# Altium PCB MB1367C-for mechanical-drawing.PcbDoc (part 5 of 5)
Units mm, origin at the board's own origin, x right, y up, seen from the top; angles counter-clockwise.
Board outline 70 x 82.5 mm, 4 copper layers (Top Layer, Signal Layer 1, Signal Layer 2, Bottom Layer), stack 1.614 mm thick; 191 components, 143 nets, 808 pads, 920 vias.
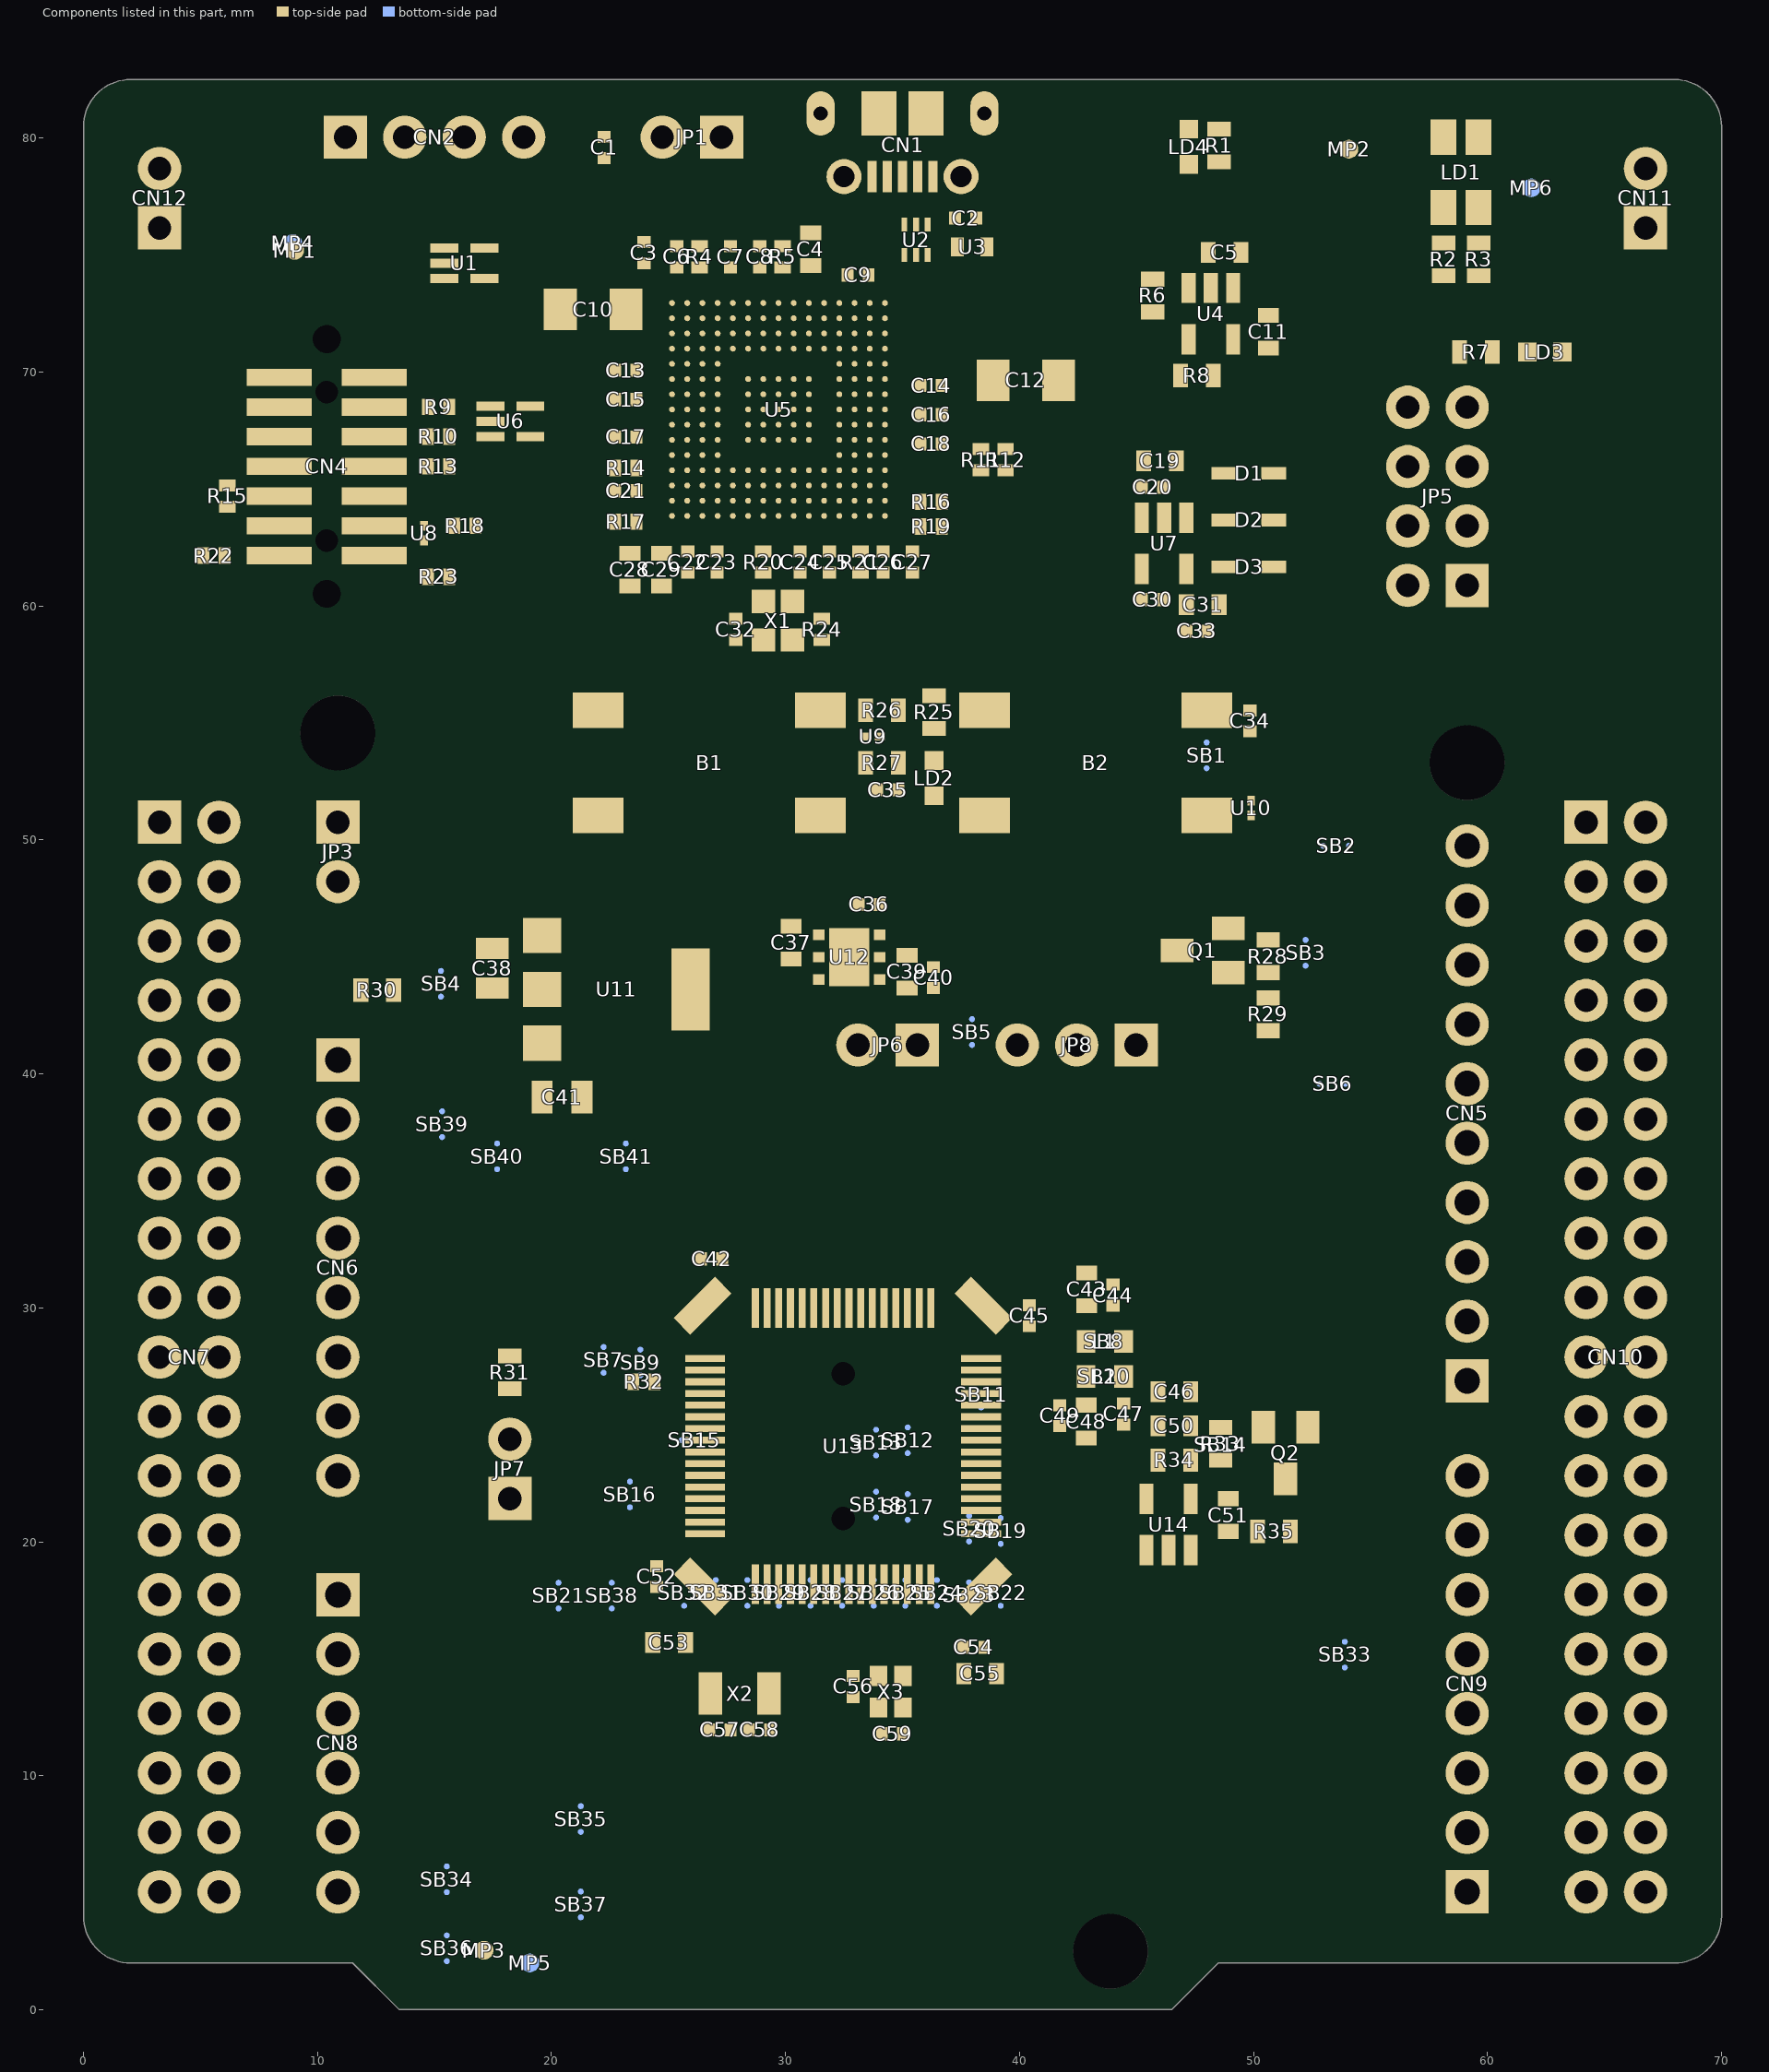
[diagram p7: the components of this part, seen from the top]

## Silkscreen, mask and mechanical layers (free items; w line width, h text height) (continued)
Drill Drawing:
  drawing of 339 lines, arcs and shapes, not listed
  text "« THE COMPONENTS WITH PLATED THROUGH HOLE (PTH) MAY BE WELDED (CABLED) IN \"PIN-IN-PASTE\" MODE (IF NECESSARY) »" at 16.925,136.875 h3.5
  text "PCB SPECIFICATIONS :" at 0.67,130.815 h3
  text "**Plating type :" at 117.72,130.465 h2.5
  text "A.   MATERIAL :" at 0.67,126.815 h3
  text "FR-4" at 39.17,126.815 h3
  text "TG-170" at 55.67,126.815 h3
  text "X  TG-150" at 73.92,126.815 h3
  text "TG-140" at 89.92,126.815 h3
  text "lead Gold" at 124.445,125.99 h2.5
  text "B.   MATERIAL FAMILY :" at 0.67,123.815 h3
  text "N/A" at 39.17,123.815 h3
  text "C.   SOLDERMASK COLOR :" at 0.67,120.815 h3
  text "GREEN" at 39.17,120.815 h3
  text "X  WHITE" at 55.67,120.815 h3
  text "RED" at 73.92,120.815 h3
  text "BLACK" at 89.92,120.815 h3
  text "D.   SILKSCREEN COLOR :" at 0.67,117.815 h3
  text "WHITE" at 39.17,117.815 h3
  text "YELLOW" at 55.67,117.815 h3
  text "BLACK" at 73.92,117.815 h3
  text "X  Blue ink PANTONE 2955" at 89.92,117.815 h3
  text "E.   SURFACE FINISH :" at 0.67,114.815 h3
  text "X  ENIG" at 39.17,114.815 h3
  text "IMMERSION SILVER" at 55.67,114.815 h3
  text "IMMERSION TIN" at 89.92,114.815 h3
  text "HASL" at 39.17,111.815 h3
  text "HASL (PB-FREE)" at 55.67,111.815 h3
  text "GOLDEN FINGER" at 89.92,111.815 h3
  text "F.   IMPEDANCE CONTROL :" at 0.67,108.815 h3
  text "NO" at 39.17,108.815 h3
  text "X  YES  (SEE IMPEDANCE TABLE FOR DETAIL INFORMATION)" at 55.67,108.815 h3
  text "G.   THROUGH VIA :" at 0.67,105.815 h3
  text "PLUG THE VIAS WHICH ARE COVERED WITH SOLDERMASK ONE OR TWO SIDE." at 39.17,105.815 h3
  text "PLUG MATERIAL :" at 39.17,102.815 h3
  text "X  SOLDERMASK" at 64.67,102.815 h3
  text "NON-CONDUCTIVE EPOXY." at 89.92,102.815 h3
  text "H.   STACK-UP :" at 0.67,99.815 h3
  text "SEE LAYER STACK-UP SEQUENCE FOR OVERALL THICKNESS." at 39.17,99.815 h3
  text "Layer" at 79.198,93.05 h2
  text "Name" at 87.572,93.05 h2
  text "Material" at 103.769,93.05 h2
  text "Thickness" at 118.323,93.05 h2
  text "Constant" at 130.278,93.05 h2
  text "Board Layer Stack" at 141.342,93.05 h2
  text "1" at 79.198,89.05 h2
  text "Top Overlay" at 87.572,89.05 h2
  text "PCB : TYPE 3" at 166.351,87.363 h3
  text "2" at 79.198,85.05 h2
  text "Top Solder" at 87.572,85.05 h2
  text "Solder Resist" at 103.769,85.05 h2
  text "0,015mm" at 118.323,85.05 h2
  text "3,5" at 130.278,85.05 h2
  text "ASPECT-RATIO, AXE Z :" at 166.351,81.863 h3
  text "3" at 79.198,81.05 h2
  text "Top Layer" at 87.572,81.05 h2
  text "Copper" at 103.769,81.05 h2
  text "0,042mm" at 118.323,81.05 h2
  text "4" at 79.198,77.05 h2
  text "Dielectric 1" at 87.572,77.05 h2
  text "PP-IT-180A" at 103.769,77.05 h2
  text "0,106mm" at 118.323,77.05 h2
  text "4,2" at 130.278,77.05 h2
  text "6:1 to 8:1 / LEVEL \"B\"" at 166.37,75.115 h3
  text "5" at 79.198,73.05 h2
  text "Signal Layer 1" at 87.572,73.05 h2
  text "Copper" at 103.769,73.05 h2
  text "0,035mm" at 118.323,73.05 h2
  text "6" at 79.198,69.05 h2
  text "Dielectric 2" at 87.572,69.05 h2
  text "FR4" at 103.769,69.05 h2
  text "1,248mm" at 118.323,69.05 h2
  text "4,2" at 130.278,69.05 h2
  text "MINIMUM PARAMETERS" at 166.595,65.99 h3
  text "7" at 79.198,65.05 h2
  text "Signal Layer 2" at 87.572,65.05 h2
  text "Copper" at 103.769,65.05 h2
  text "0,035mm" at 118.323,65.05 h2
  text "8" at 79.198,61.05 h2
  text "Dielectric 3" at 87.572,61.05 h2
  text "PP-IT-180A" at 103.769,61.05 h2
  text "0,106mm" at 118.323,61.05 h2
  text "4,2" at 130.278,61.05 h2
  text "DEFAULT" at 166.595,60.49 h3
  text "9" at 79.198,57.05 h2
  text "Bottom Layer" at 87.572,57.05 h2
  text "Copper" at 103.769,57.05 h2
  text "0,042mm" at 118.323,57.05 h2
  text "TRACKS : 0.120mm           / GAPS : 0.120mm" at 166.595,54.74 h3
  text "10" at 79.198,53.05 h2
  text "Bottom Solder" at 87.572,53.05 h2
  text "Solder Resist" at 103.769,53.05 h2
  text "0,015mm" at 118.323,53.05 h2
  text "3,5" at 130.278,53.05 h2
  text "11" at 79.198,49.05 h2
  text "Bottom Overlay" at 87.572,49.05 h2
  text "Symbol" at 87.771,42.179 h2.4
  text "Count" at 97.17,42.179 h2.4
  text "Hole Size" at 107.801,42.179 h2.4
  text "Plated" at 127.073,42.179 h2.4
  text "Hole Type" at 135.324,42.179 h2.4
  text "Drill Layer Pair" at 147.335,42.179 h2.4
  text "Via/Pad" at 170.115,42.179 h2.4
  text "Hole Length" at 179.958,42.179 h2.4
  text "Routed Path Length" at 198.115,42.179 h2.4
  text "920" at 97.17,38.036 h2
  text "0,200mm (7,87mil)" at 107.801,38.036 h2
  text "PTH" at 127.073,38.036 h2
  text "Round" at 135.324,38.036 h2
  text "Top Layer - Bottom Layer" at 147.335,38.036 h2
  text "Via" at 170.115,38.036 h2
  text "-" at 179.958,38.036 h2
  text "-" at 198.115,38.036 h2
  text "0,20" at 87.851,37.475 h1.84
  text "2" at 97.17,33.892 h2
  text "0,600mm (23,62mil)" at 107.801,33.892 h2
  text "PTH" at 127.073,33.892 h2
  text "Slot" at 135.324,33.892 h2
  text "Top Layer - Bottom Layer" at 147.335,33.892 h2
  text "Pad" at 170.115,33.892 h2
  text "1,300mm (51,18mil)" at 179.958,33.892 h2
  text "0,700mm (27,56mil)" at 198.115,33.892 h2
  text "0,60" at 87.851,33.332 h1.84
  text "2" at 97.17,29.749 h2
  text "0,900mm (35,43mil)" at 107.801,29.749 h2
  text "PTH" at 127.073,29.749 h2
  text "Round" at 135.324,29.749 h2
  text "Top Layer - Bottom Layer" at 147.335,29.749 h2
  text "Pad" at 170.115,29.749 h2
  text "-" at 179.958,29.749 h2
  text "-" at 198.115,29.749 h2
  text "0,90" at 87.851,29.189 h1.84
  text "2" at 97.17,25.606 h2
  text "0,970mm (38,19mil)" at 107.801,25.606 h2
  text "NPTH" at 127.073,25.606 h2
  text "Round" at 135.324,25.606 h2
  text "Top Layer - Bottom Layer" at 147.335,25.606 h2
  text "Pad" at 170.115,25.606 h2
  text "-" at 179.958,25.606 h2
  text "-" at 198.115,25.606 h2
  text "0,97" at 87.851,25.046 h1.84
  text "2" at 97.17,21.463 h2
  text "1,000mm (39,37mil)" at 107.801,21.463 h2
  text "NPTH" at 127.073,21.463 h2
  text "Round" at 135.324,21.463 h2
  text "Top Layer - Bottom Layer" at 147.335,21.463 h2
  text "Pad" at 170.115,21.463 h2
  text "-" at 179.958,21.463 h2
  text "-" at 198.115,21.463 h2
  text "1,00" at 87.851,20.903 h1.84
  text "103" at 97.17,17.32 h2
  text "1,000mm (39,37mil)" at 107.801,17.32 h2
  text "PTH" at 127.073,17.32 h2
  text "Round" at 135.324,17.32 h2
  text "Top Layer - Bottom Layer" at 147.335,17.32 h2
  text "Pad" at 170.115,17.32 h2
  text "-" at 179.958,17.32 h2
  text "-" at 198.115,17.32 h2
  text "1,00" at 87.851,16.76 h1.84
  text "32" at 97.17,13.177 h2
  text "1,100mm (43,31mil)" at 107.801,13.177 h2
  text "PTH" at 127.073,13.177 h2
  text "Round" at 135.324,13.177 h2
  text "Top Layer - Bottom Layer" at 147.335,13.177 h2
  text "Pad" at 170.115,13.177 h2
  text "-" at 179.958,13.177 h2
  text "-" at 198.115,13.177 h2
  text "1,10" at 87.851,12.617 h1.84
  text "2" at 97.17,9.034 h2
  text "1,190mm (46,85mil)" at 107.801,9.034 h2
  text "NPTH" at 127.073,9.034 h2
  text "Round" at 135.324,9.034 h2
  text "Top Layer - Bottom Layer" at 147.335,9.034 h2
  text "Pad" at 170.115,9.034 h2
  text "-" at 179.958,9.034 h2
  text "-" at 198.115,9.034 h2
  text "1,19" at 87.851,8.473 h1.84
  text "3" at 97.17,4.891 h2
  text "3,200mm (125,98mil)" at 107.801,4.891 h2
  text "NPTH" at 127.073,4.891 h2
  text "Round" at 135.324,4.891 h2
  text "Top Layer - Bottom Layer" at 147.335,4.891 h2
  text "Pad" at 170.115,4.891 h2
  text "-" at 179.958,4.891 h2
  text "-" at 198.115,4.891 h2
  text "3,20" at 87.851,4.33 h1.84
  text "1068 Total" at 97.17,0.748 h2
  text "Slot definitions :" at 87.771,-2.152 h2
  text "Routed Path Length" at 101.424,-2.152 h2
  text "= Calculated from tool start centre position to tool end centre position." at 118.338,-2.152 h2
  text "Hole Length" at 101.424,-3.81 h2
  text "= Routed Path Length + Tool Size = Slot length as defined in the PCB layout" at 112.059,-3.81 h2
  text "IMPEDANCE TABLE" at 100.045,-10.385 h3
  text "LAYER" at 104.295,-15.385 h3
  text "TRACE" at 120.545,-15.385 h3
  text "SPACING" at 131.045,-15.385 h3
  text "IMPEDANCE" at 144.545,-15.385 h3
  text "IMPEDANCE" at 161.545,-15.385 h3
  text "TOL." at 180.295,-15.385 h3
  text "(mm)" at 134.37,-17.86 h2.5
  text "(mm)" at 122.545,-17.91 h2.5
  text "(Single ended)" at 145.045,-18.135 h2.5
  text "(Differentiel)" at 162.795,-18.135 h2.5
  text "0.160" at 121.52,-21.86 h3
  text "NA" at 150.145,-21.86 h3
  text "0.226" at 133.545,-21.885 h3
  text "90 ohm" at 164.795,-21.885 h3
  text "+/- 10%" at 178.795,-21.885 h3
  text "TOP" at 105.445,-21.91 h3

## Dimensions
59.13,53.3 to 2,82.5 on M2-Board Dimensions
59.13,53.3 to 70,80.5 on M2-Board Dimensions
13.5,0 to 11.5,2 on M2-Board Dimensions
66.75,5.04 to 46.5,0 on M2-Board Dimensions
66.75,78.7 to 68,82.5 on M2-Board Dimensions
0,80.5 to 10.87,54.57 on M2-Board Dimensions
3.25,78.7 to 66.75,78.7 on M2-Board Dimensions
10.87,54.57 to 2,82.5 on M2-Board Dimensions
13.5,0 to 46.5,0 on M2-Board Dimensions
70,0.125 to 43.89,2.5 on M2-Board Dimensions
10.87,5.04 to 59.13,5.04 on M2-Board Dimensions
66.75,5.04 to 3.25,5.04 on M2-Board Dimensions
0,4 to 70,4 on M2-Board Dimensions
2,82.5 to 13.5,0 on M2-Board Dimensions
